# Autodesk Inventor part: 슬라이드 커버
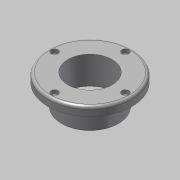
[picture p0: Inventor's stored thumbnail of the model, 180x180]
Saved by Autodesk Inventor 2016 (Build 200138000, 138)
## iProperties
Created: 2015-10
Part Number: 슬라이드 커버
Document SubType Name: Modeling
Designer: mdu
Density: 7.86 g/cm^3
Material: 강철, 연강
Mass: 598.523 g
Surface Area: 229.996 cm^2
Volume: 76.148 cm^3
Appearance: 강철
Author: mdu
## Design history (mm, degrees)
sketch "스케치1"
  geometry: C1 r 47.5 at (0, 0); C2 r 32.5 at (0, 0); 1 further point
  constraints: 2 centre point, 2 coincident
  dimensions: "d33" = 95 diameter of C1; "d35" = 65 diameter of C2
extrude "돌출1" new body sketch "스케치1" distance "d0" = 10; taper "d1" = 0 deg
extrude "돌출2" join sketch "스케치1" distance "d2" = 25; taper "d3" = 0 deg
hole "구멍1" diameter "d6" = 50; stored, may be unused: countersink angle "d10" = 90 deg, drill point angle "d12" = 118 deg; dims "d4" = 10, "d5" = 10, "d7" = 6, "d8" = 4, "d9" = 2, "d11" = 8
sketch "스케치2" dims "d36" = 80
  geometry: 4 further points
  constraints: 2 coincident, 2 vertical alignment, 2 other
hole "구멍2" sketch "스케치2" at (0, 40) diameter "d13" = 4.5; stored, may be unused: countersink angle "d17" = 90 deg, drill point angle "d19" = 118 deg; dims "d14" = 6, "d15" = 8, "d16" = 4.4, "d18" = 8
fillet "모깎기1" dims "d23" = 3
chamfer "모따기1" distance "d24" = 1; stored, may be unused: second distance "d25" = 2, angle "d26" = 45 deg
sketch "스케치3"
  geometry: C1 r 25 at (0, 0); C2 r 30 at (0, 0); C3 r 26 at (0, 0) reference; 1 further point
  constraints: 2 centre point, 2 coincident
  dimensions: "d27" = 60 diameter of C2
extrude "돌출3" cut sketch "스케치3" distance "d28" = 3; taper "d29" = 0 deg
chamfer "모따기2" distance "d30" = 1; stored, may be unused: second distance "d31" = 2, angle "d32" = 45 deg
node "솔리드1"
pattern_circular "원형 패턴1" dims angle "d21" = 360 deg
